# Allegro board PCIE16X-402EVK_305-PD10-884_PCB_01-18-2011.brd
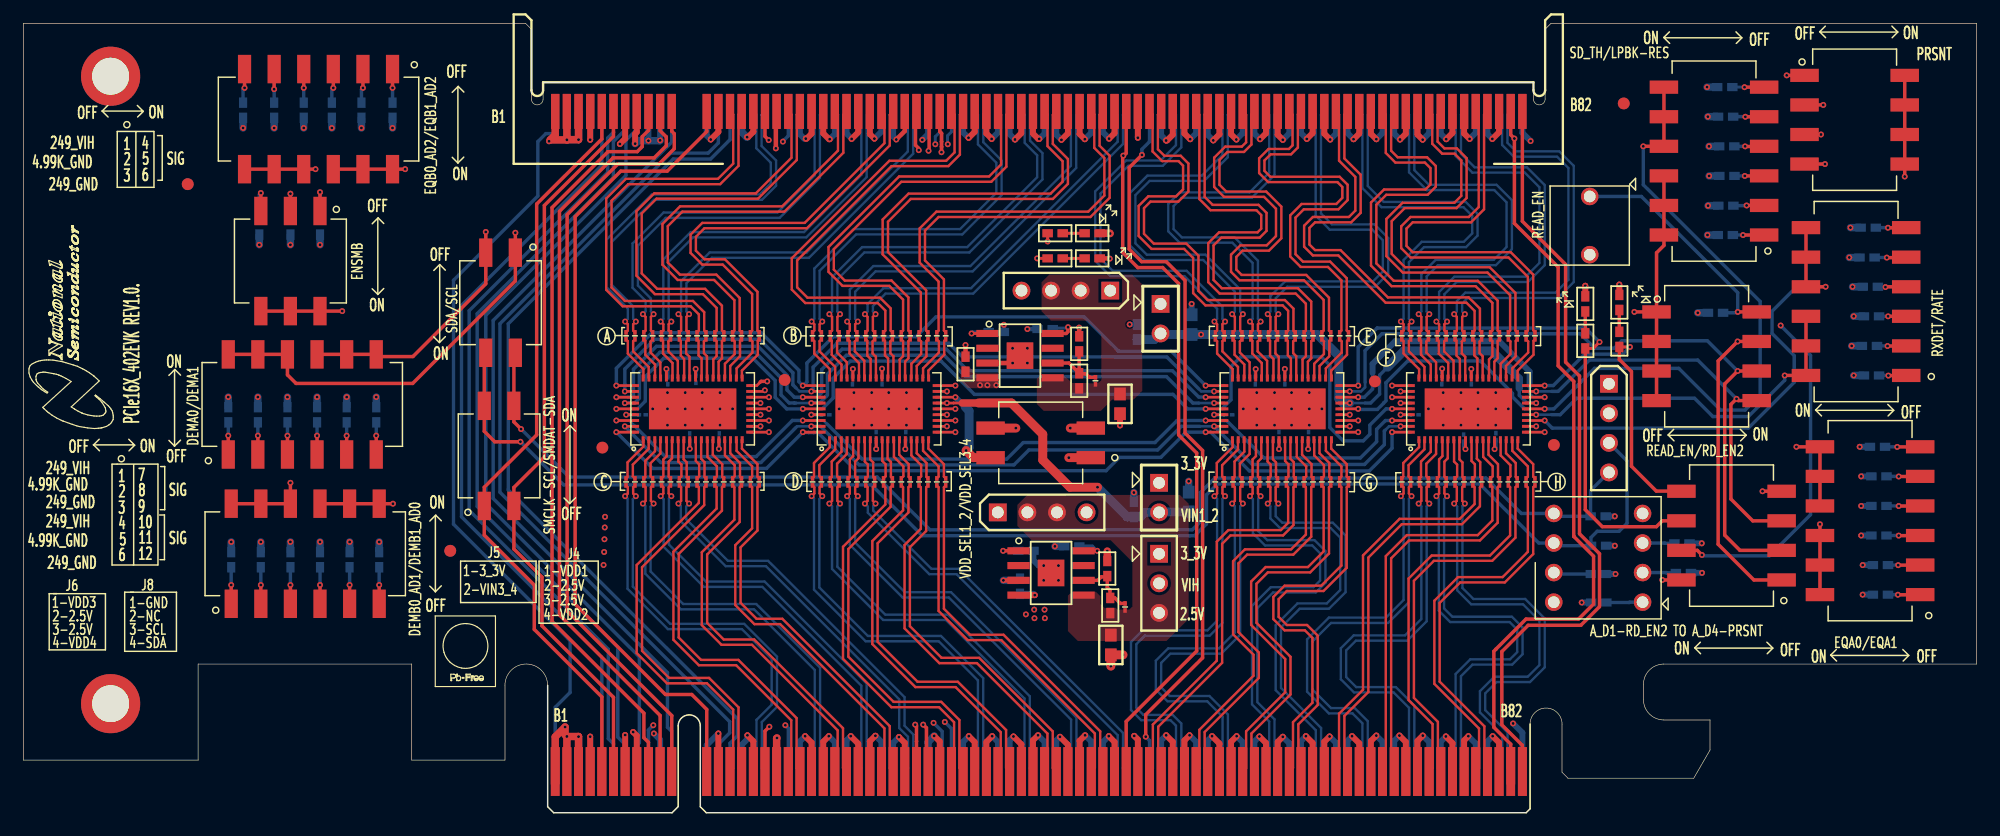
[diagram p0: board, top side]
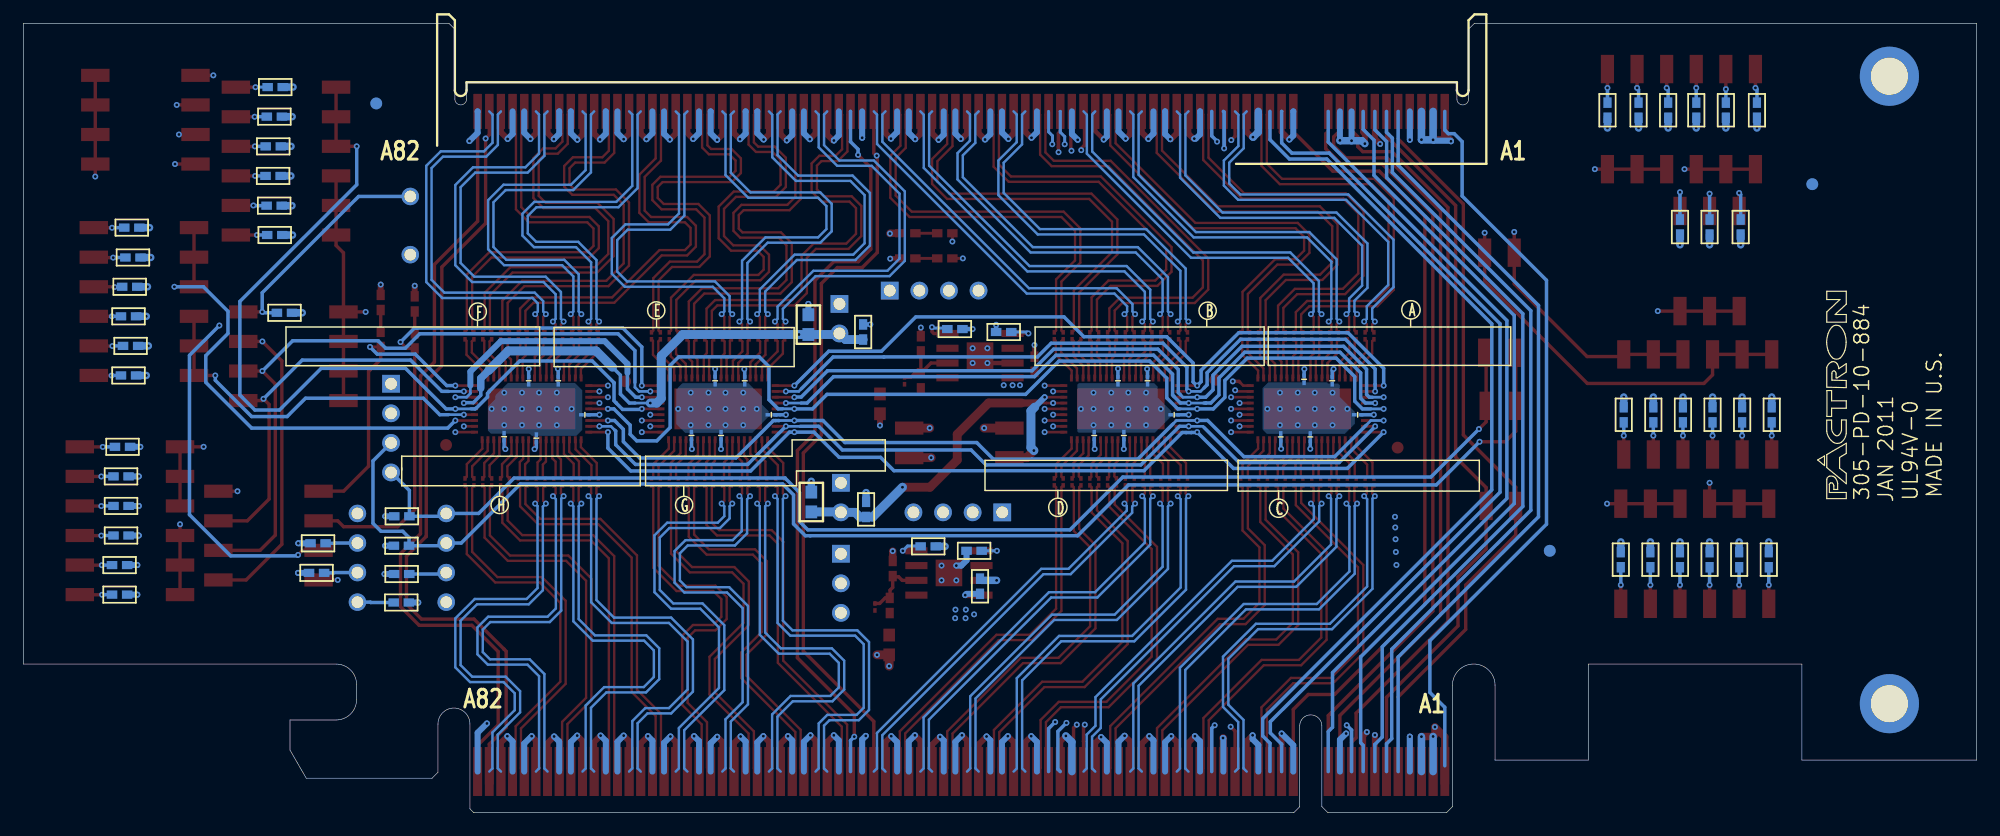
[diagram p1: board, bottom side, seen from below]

Outline 167.64 x 67.82 mm; copper layers: TOP, GND1, POWER1, POWER2, GND2, BOTTOM. Coordinates in mm from the lower left corner of the outline.
Outline path: 0,67.82 0,4.52 15,4.52 15,12.77 33.33,12.77 33.33,4.52 41.34,4.52 41.34,10.95 arc(43.16,12.77) 44.99,10.95 44.99,0.52 45.51,0 55.68,0 56.2,0.52 56.2,7.47 arc(57.15,8.42) 58.1,7.47 58.1,0.51 58.61,0 128.98,0 129.31,0.34 129.31,7.62 arc(130.68,8.99) 132.05,7.62 132.05,3.47 132.56,2.97 143.36,2.97 144.75,5.39 144.75,7.97 140.79,7.97 arc(139.55,8.48) 139.04,9.72 139.04,11.02 arc(139.55,12.26) 140.79,12.77 167.64,12.77 167.64,67.82 131.11,67.82 130.6,67.31 130.6,61.31 arc(130.1,60.81) 129.6,61.31 129.6,62.74 44.61,62.74 44.61,61.31 arc(44.11,60.81) 43.61,61.31 43.61,67.31 43.1,67.82 0,67.82

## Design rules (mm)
net group 3_3V: nets N14347847 N14379914
net group A_D1: nets A_D1 N144905650
net group A_D2: nets A_D2 N144912360
net group A_D3: nets A_D3 N144909880
net group A_D4: nets A_D4 N144914850
net group PERN0: nets N708449616 PERN0
net group PERN0_C: nets N144793501 PERN0_C
net group PERN1: nets N708449621 PERN1
net group PERN1_C: nets N144768421 PERN1_C
net group PERN2: nets N708449625 PERN2
net group PERN2_C: nets N144768181 PERN2_C
net group PERN3: nets N708449629 PERN3
net group PERN3_C: nets N144794701 PERN3_C
net group PERN4: nets N708449635 PERN4
net group PERN4_C: nets N144796981 PERN4_C
net group PERN5: nets N708449639 PERN5
net group PERN5_C: nets N144780601 PERN5_C
net group PERN6: nets N708449643 PERN6
net group PERN6_C: nets N144778981 PERN6_C
net group PERN7: nets N708449647 PERN7
net group PERN7_C: nets N144766261 PERN7_C
net group PERN8: nets N708449652 PERN8
net group PERN8_C: nets N144777781 PERN8_C
net group PERN9: nets N708449656 PERN9
net group PERN9_C: nets N144778201 PERN9_C
net group PERN10: nets N708449660 PERN10
net group PERN10_C: nets N144778741 PERN10_C
net group PERN11: nets N708449664 PERN11
net group PERN11_C: nets N144777421 PERN11_C
net group PERN12: nets N708449668 PERN12
net group PERN12_C: nets N144796741 PERN12_C
net group PERN13: nets N708449672 PERN13
net group PERN13_C: nets N144769921 PERN13_C
net group PERN14: nets N708449676 PERN14
net group PERN14_C: nets N144775501 PERN14_C
net group PERN15: nets N708449680 PERN15
net group PERN15_C: nets N144767221 PERN15_C
net group PERP0: nets N708449615 PERP0
net group PERP0_C: nets N144792241 PERP0_C
net group PERP1: nets N708449620 PERP1
net group PERP1_C: nets N144791101 PERP1_C
net group PERP2: nets N708449624 PERP2
net group PERP2_C: nets N144794401 PERP2_C
net group PERP3: nets N708449628 PERP3
net group PERP3_C: nets N144773581 PERP3_C
net group PERP4: nets N708449634 PERP4
net group PERP4_C: nets N144792841 PERP4_C
net group PERP5: nets N708449638 PERP5
net group PERP5_C: nets N144771181 PERP5_C
net group PERP6: nets N708449642 PERP6
net group PERP6_C: nets N144780361 PERP6_C
net group PERP7: nets N708449646 PERP7
net group PERP7_C: nets N144773341 PERP7_C
net group PERP8: nets N708449651 PERP8
net group PERP8_C: nets N144769021 PERP8_C
net group PERP9: nets N708449655 PERP9
net group PERP9_C: nets N144788821 PERP9_C
net group PERP10: nets N708449659 PERP10
net group PERP10_C: nets N144768781 PERP10_C
net group PERP11: nets N708449663 PERP11
net group PERP11_C: nets N144772741 PERP11_C
net group PERP12: nets N708449667 PERP12
net group PERP12_C: nets N144777181 PERP12_C
net group PERP13: nets N708449671 PERP13
net group PERP13_C: nets N144766561 PERP13_C
net group PERP14: nets N708449675 PERP14
net group PERP14_C: nets N144795421 PERP14_C
net group PERP15: nets N708449679 PERP15
net group PERP15_C: nets N144788221 PERP15_C
net group PETN0: nets N708449696 PETN0
net group PETN0_C: nets N144795060 PETN0_C
net group PETN1: nets N7084496101 PETN1
net group PETN1_C: nets N144774480 PETN1_C
net group PETN2: nets N7084496105 PETN2
net group PETN2_C: nets N144776640 PETN2_C
net group PETN3: nets N7084496109 PETN3
net group PETN3_C: nets N144771900 PETN3_C
net group PETN4: nets N7084496115 PETN4
net group PETN4_C: nets N144790620 PETN4_C
net group PETN5: nets N7084496119 PETN5
net group PETN5_C: nets N144770280 PETN5_C
net group PETN6: nets N7084496123 PETN6
net group PETN6_C: nets N144771420 PETN6_C
net group PETN7: nets N7084496127 PETN7
net group PETN7_C: nets N144775140 PETN7_C
net group PETN8: nets N7084496132 PETN8
net group PETN8_C: nets N144795720 PETN8_C
net group PETN9: nets N7084496136 PETN9
net group PETN9_C: nets N144776160 PETN9_C
net group PETN10: nets N7084496140 PETN10
net group PETN10_C: nets N144770880 PETN10_C
net group PETN11: nets N7084496144 PETN11
net group PETN11_C: nets N144790260 PETN11_C
net group PETN12: nets N7084496148 PETN12
net group PETN12_C: nets N144772500 PETN12_C
net group PETN13: nets N7084496152 PETN13
net group PETN13_C: nets N144778500 PETN13_C
net group PETN14: nets N7084496156 PETN14
net group PETN14_C: nets N144774000 PETN14_C
net group PETN15: nets N7084496160 PETN15
net group PETN15_C: nets N144791880 PETN15_C
net group PETP0: nets N708449695 PETP0
net group PETP0_C: nets N144769680 PETP0_C
net group PETP1: nets N7084496100 PETP1
net group PETP1_C: nets N144776880 PETP1_C
net group PETP2: nets N7084496104 PETP2
net group PETP2_C: nets N144766980 PETP2_C
net group PETP3: nets N7084496108 PETP3
net group PETP3_C: nets N144779460 PETP3_C
net group PETP4: nets N7084496114 PETP4
net group PETP4_C: nets N144779220 PETP4_C
net group PETP5: nets N7084496118 PETP5
net group PETP5_C: nets N144796260 PETP5_C
net group PETP6: nets N7084496122 PETP6
net group PETP6_C: nets N144789780 PETP6_C
net group PETP7: nets N7084496126 PETP7
net group PETP7_C: nets N144765660 PETP7_C
net group PETP8: nets N7084496131 PETP8
net group PETP8_C: nets N144789240 PETP8_C
net group PETP9: nets N7084496135 PETP9
net group PETP9_C: nets N144794040 PETP9_C
net group PETP10: nets N7084496139 PETP10
net group PETP10_C: nets N144770640 PETP10_C
net group PETP11: nets N7084496143 PETP11
net group PETP11_C: nets N144774240 PETP11_C
net group PETP12: nets N7084496147 PETP12
net group PETP12_C: nets N144793080 PETP12_C
net group PETP13: nets N7084496151 PETP13
net group PETP13_C: nets N144780060 PETP13_C
net group PETP14: nets N7084496155 PETP14
net group PETP14_C: nets N144767760 PETP14_C
net group PETP15: nets N7084496159 PETP15
net group PETP15_C: nets N144772140 PETP15_C
net group VOUT1_2: nets N14347575 VOUT1_2
net group VOUT3_4: nets N14379574 VOUT3_4
net group SCL: nets N14519010 N14693554 N143603151 N143605671 N144870781 N144872810 N144872813 N144873671 N144875811 N144883340 N144883343 N144883781 N144885701 N144890181 N144891221 SCL SDA

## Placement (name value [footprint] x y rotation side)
C1  0.1uF  [0201]  57.19 32.28 270 bottom
C2  0.1uF  [0201]  53.12 34.19 180 bottom
C3  0.1uF  [0201]  57.72 37.23 90 bottom
C4  0.1uF  [0201]  55.31 37.11 90 bottom
C5  0.1uF  [0201]  59.73 32.28 270 bottom
C6  0.1uF  [0201]  73.7 37.11 90 bottom
C7  0.1uF  [0201]  71.16 37.11 90 bottom
C8  0.1uF  [0201]  68.87 34.19 180 bottom
C9  0.1uF  [0201]  73.19 32.41 270 bottom
C10  0.1uF  [0201]  75.73 32.41 270 bottom
C11  0.1uF  [0201]  110.3 32.41 270 bottom
C12  0.1uF  [0201]  107.76 32.41 270 bottom
C13  0.1uF  [0201]  103.44 34.19 180 bottom
C14  0.1uF  [0201]  108.27 37.11 90 bottom
C15  0.1uF  [0201]  105.73 37.11 90 bottom
C16  0.1uF  [0201]  126.38 32.31 270 bottom
C17  0.1uF  [0201]  123.61 32.18 270 bottom
C18  0.1uF  [0201]  119.44 34.19 180 bottom
C19  0.1uF  [0201]  124.27 37.11 90 bottom
C20  0.1uF  [0201]  121.73 37.11 90 bottom
C21  10uF  [0603]  100.01 26.69 270 bottom
C22  10uF  [0603]  100.27 41.93 270 bottom
C23  4.7uF  [0402]  85.53 19.45 270 bottom
C24  4.7uF  [0402]  80.86 38.53 270 top
C25  0.01uF  [0402]  86.04 22.5 0 bottom
C26  0.01uF  [0402]  83.5 41.3 0 bottom
C27  10uF  [0603]  93.33 14.41 270 top
C28  10uF  [0603]  94.12 35.12 270 top
C29  1nF  [0201]  94.55 17.68 90 top
C30  1nF  [0201]  92.01 37.11 90 top
C31  0.22uF  [0201]  57.82 28.42 90 top
C32  0.22uF  [0201]  58.59 28.42 90 top
C33  0.22uF  [0201]  59.35 28.42 90 top
C34  0.22uF  [0201]  60.11 28.42 90 top
C35  0.22uF  [0201]  60.87 28.42 90 top
C36  0.22uF  [0201]  61.63 28.42 90 top
C37  0.22uF  [0201]  62.4 28.42 90 top
C38  0.22uF  [0201]  63.16 28.42 90 top
C39  0.22uF  [0201]  73.83 28.42 90 top
C40  0.22uF  [0201]  74.59 28.42 90 top
C41  0.22uF  [0201]  75.35 28.42 90 top
C42  0.22uF  [0201]  76.11 28.42 90 top
C43  0.22uF  [0201]  76.87 28.42 90 top
C44  0.22uF  [0201]  77.64 28.42 90 top
C45  0.22uF  [0201]  78.4 28.42 90 top
C46  0.22uF  [0201]  79.16 28.42 90 top
C47  0.22uF  [0201]  108.39 28.42 90 top
C48  0.22uF  [0201]  109.16 28.42 90 top
C49  0.22uF  [0201]  109.92 28.42 90 top
C50  0.22uF  [0201]  110.68 28.42 90 top
C51  0.22uF  [0201]  111.44 28.42 90 top
C52  0.22uF  [0201]  112.2 28.42 90 top
C53  0.22uF  [0201]  112.97 28.42 90 top
C54  0.22uF  [0201]  113.73 28.42 90 top
C55  0.22uF  [0201]  124.4 28.42 90 top
C56  0.22uF  [0201]  125.16 28.42 90 top
C57  0.22uF  [0201]  125.92 28.42 90 top
C58  0.22uF  [0201]  126.68 28.42 90 top
C59  0.22uF  [0201]  127.44 28.42 90 top
C60  0.22uF  [0201]  128.21 28.42 90 top
C61  0.22uF  [0201]  128.97 28.42 90 top
C62  0.22uF  [0201]  129.73 28.42 90 top
C63  0.22uF  [0201]  51.73 28.42 270 top
C64  0.22uF  [0201]  52.49 28.42 270 top
C65  0.22uF  [0201]  53.25 28.42 270 top
C66  0.22uF  [0201]  54.01 28.42 270 top
C67  0.22uF  [0201]  54.78 28.42 270 top
C68  0.22uF  [0201]  55.54 28.42 270 top
C69  0.22uF  [0201]  56.3 28.42 270 top
C70  0.22uF  [0201]  57.06 28.42 270 top
C71  0.22uF  [0201]  67.73 28.42 270 top
C72  0.22uF  [0201]  68.49 28.42 270 top
C73  0.22uF  [0201]  69.25 28.42 270 top
C74  0.22uF  [0201]  70.02 28.42 270 top
C75  0.22uF  [0201]  70.78 28.42 270 top
C76  0.22uF  [0201]  71.54 28.42 270 top
C77  0.22uF  [0201]  72.3 28.42 270 top
C78  0.22uF  [0201]  73.06 28.42 270 top
C79  0.22uF  [0201]  102.3 28.42 270 top
C80  0.22uF  [0201]  103.06 28.42 270 top
C81  0.22uF  [0201]  103.82 28.42 270 top
C82  0.22uF  [0201]  104.58 28.42 270 top
C83  0.22uF  [0201]  105.35 28.42 270 top
C84  0.22uF  [0201]  106.11 28.42 270 top
C85  0.22uF  [0201]  106.87 28.42 270 top
C86  0.22uF  [0201]  107.63 28.42 270 top
C87  0.22uF  [0201]  118.3 28.42 270 top
C88  0.22uF  [0201]  119.06 28.42 270 top
C89  0.22uF  [0201]  119.82 28.42 270 top
C90  0.22uF  [0201]  120.59 28.42 270 top
C91  0.22uF  [0201]  121.35 28.42 270 top
C92  0.22uF  [0201]  122.11 28.42 270 top
C93  0.22uF  [0201]  122.87 28.42 270 top
C94  0.22uF  [0201]  123.63 28.42 270 top
C95  0.22uF  [0201]  57.82 40.97 270 top
C96  0.22uF  [0201]  58.59 40.97 270 top
C97  0.22uF  [0201]  59.35 40.97 270 top
C98  0.22uF  [0201]  60.11 40.97 270 top
C99  0.22uF  [0201]  60.87 40.97 270 top
C100  0.22uF  [0201]  61.63 40.97 270 top
C101  0.22uF  [0201]  62.4 40.97 270 top
C102  0.22uF  [0201]  63.16 40.97 270 top
C103  0.22uF  [0201]  73.83 40.97 270 top
C104  0.22uF  [0201]  74.59 40.97 270 top
C105  0.22uF  [0201]  75.35 40.97 270 top
C106  0.22uF  [0201]  76.11 40.97 270 top
C107  0.22uF  [0201]  76.87 40.97 270 top
C108  0.22uF  [0201]  77.64 40.97 270 top
C109  0.22uF  [0201]  78.4 40.97 270 top
C110  0.22uF  [0201]  79.16 40.97 270 top
C111  0.22uF  [0201]  108.39 40.97 270 top
C112  0.22uF  [0201]  109.16 40.97 270 top
C113  0.22uF  [0201]  109.92 40.97 270 top
C114  0.22uF  [0201]  110.68 40.97 270 top
C115  0.22uF  [0201]  111.44 40.97 270 top
C116  0.22uF  [0201]  112.2 40.97 270 top
C117  0.22uF  [0201]  112.97 40.97 270 top
C118  0.22uF  [0201]  113.73 40.97 270 top
C119  0.22uF  [0201]  124.4 40.97 270 top
C120  0.22uF  [0201]  125.16 40.97 270 top
C121  0.22uF  [0201]  125.92 40.97 270 top
C122  0.22uF  [0201]  126.68 40.97 270 top
C123  0.22uF  [0201]  127.44 40.97 270 top
C124  0.22uF  [0201]  128.21 40.97 270 top
C125  0.22uF  [0201]  128.97 40.97 270 top
C126  0.22uF  [0201]  129.73 40.97 270 top
C127  0.22uF  [0201]  51.73 40.97 90 top
C128  0.22uF  [0201]  52.49 40.97 90 top
C129  0.22uF  [0201]  53.25 40.97 90 top
C130  0.22uF  [0201]  54.01 40.97 90 top
C131  0.22uF  [0201]  54.78 40.97 90 top
C132  0.22uF  [0201]  55.54 40.97 90 top
C133  0.22uF  [0201]  56.3 40.97 90 top
C134  0.22uF  [0201]  57.06 40.97 90 top
C135  0.22uF  [0201]  67.73 40.97 90 top
C136  0.22uF  [0201]  68.49 40.97 90 top
C137  0.22uF  [0201]  69.25 40.97 90 top
C138  0.22uF  [0201]  70.02 40.97 90 top
C139  0.22uF  [0201]  70.78 40.97 90 top
C140  0.22uF  [0201]  71.54 40.97 90 top
C141  0.22uF  [0201]  72.3 40.97 90 top
C142  0.22uF  [0201]  73.06 40.97 90 top
C143  0.22uF  [0201]  102.3 40.97 90 top
C144  0.22uF  [0201]  103.06 40.97 90 top
C145  0.22uF  [0201]  103.82 40.97 90 top
C146  0.22uF  [0201]  104.58 40.97 90 top
C147  0.22uF  [0201]  105.35 40.97 90 top
C148  0.22uF  [0201]  106.11 40.97 90 top
C149  0.22uF  [0201]  106.87 40.97 90 top
C150  0.22uF  [0201]  107.63 40.97 90 top
C151  0.22uF  [0201]  118.3 40.97 90 top
C152  0.22uF  [0201]  119.06 40.97 90 top
C153  0.22uF  [0201]  119.82 40.97 90 top
C154  0.22uF  [0201]  120.59 40.97 90 top
C155  0.22uF  [0201]  121.35 40.97 90 top
C156  0.22uF  [0201]  122.11 40.97 90 top
C157  0.22uF  [0201]  122.87 40.97 90 top
C158  0.22uF  [0201]  123.63 40.97 90 top
C160  1uF  [0402]  95.31 26.06 270 bottom
C161  1uF  [0402]  95.57 41.3 270 bottom
D1  SML-P12PTT86  [SML-P12PTT86_0402]  91.73 49.78 180 top
D2  SML-P12PTT86  [SML-P12PTT86_0402]  91.73 47.62 180 top
D3  SML-P12PTT86  [SML-P12PTT86_0402]  134.05 43.71 270 top
D4  SML-P12PTT86  [SML-P12PTT86_0402]  136.97 43.84 270 top
J1  -  [PCIE_16X_EDGE_FINGER]  53.65 3.54 0 top
J2  -  [NWE82DHRN-T9410]  86.94 68.58 0 top
J3  2 HEADER  [2_HEADER]  97.47 28.34 270 top
J4  4 HEADER  [4_HEADER]  83.63 25.8 0 top
J5  2 HEADER  [2_HEADER]  97.6 43.71 270 top
J6  4 HEADER  [4_HEADER]  93.28 44.85 180 top
J7  3 HEADER  [3_HEADER]  97.47 22.25 270 top
J8  4 HEADER  [4_HEADER]  136.08 36.85 270 top
J9  4808-3004-CP  [DIP8]  135.16 21.9 90 top
NOREF  -  [unnamed]  14.11 54 0 top
NOREF#2  -  [unnamed]  36.64 22.5 0 top
NOREF#3  -  [unnamed]  115.99 37.06 0 top
NOREF#4  -  [unnamed]  49.7 31.37 0 top
NOREF#5  -  [unnamed]  7.49 63.27 0 top
NOREF#6  -  [unnamed]  7.49 9.37 0 top
NOREF#7  -  [unnamed]  65.34 37.18 0 top
NOREF#8  -  [#2]  15 12.77 0 top
NOREF#9  -  [unnamed]  137.35 60.93 0 top
NOREF#10  -  [#2]  33.33 4.52 0 top
NOREF#11  -  [#2]  167.64 12.77 90 top
NOREF#12  -  [#2]  0 68.58 0 top
NOREF#13  -  [unnamed]  131.36 31.59 0 top
NOREF#14  -  [#2]  0 4.52 90 top
NOREF#15  -  [#2]  0 4.52 0 top
NOREF#16  -  [unnamed]  137.35 60.93 180 bottom
NOREF#17  -  [unnamed]  36.64 22.5 180 bottom
NOREF#18  -  [unnamed]  14.11 54 180 bottom
R1  1.5k  [0402]  93.28 17.8 270 top
R2  1k  [0402]  93.03 20.98 270 top
R3  51k  [0402]  89.98 22.88 0 bottom
R4  1.5k  [0402]  90.61 37.11 270 top
R5  1k  [0402]  90.61 40.28 270 top
R6  51k  [0402]  87.69 41.55 0 bottom
R7  220  [0402]  88.56 49.78 180 top
R8  220  [0402]  88.56 47.62 180 top
R9  220  [0402]  134.05 40.54 270 top
R10  220  [0402]  136.97 40.66 270 top
R11  249  [0402]  31.69 60.35 90 bottom
R12  4.99k  [0402]  29.02 60.35 90 bottom
R13  249  [0402]  26.48 60.35 90 bottom
R14  249  [0402]  24.07 60.35 90 bottom
R15  4.99k  [0402]  21.53 60.35 90 bottom
R16  249  [0402]  18.86 60.35 90 bottom
R17  249  [0402]  25.46 50.31 90 bottom
R18  4.99k  [0402]  22.92 50.31 90 bottom
R19  249  [0402]  20.26 50.31 90 bottom
R20  249  [0402]  17.59 34.19 270 bottom
R21  4.99k  [0402]  20.13 34.19 270 bottom
R22  249  [0402]  22.67 34.19 270 bottom
R23  249  [0402]  25.21 34.19 270 bottom
R24  4.99k  [0402]  27.75 34.19 270 bottom
R25  249  [0402]  30.29 34.19 270 bottom
R26  249  [0402]  17.84 21.74 270 bottom
R27  4.99k  [0402]  20.38 21.74 270 bottom
R28  249  [0402]  22.92 21.74 270 bottom
R29  249  [0402]  25.46 21.74 270 bottom
R30  4.99k  [0402]  28 21.74 270 bottom
R31  249  [0402]  30.54 21.74 270 bottom
R32  249  [0402]  146.06 49.63 0 bottom
R33  4.99k  [0402]  146.11 52.15 0 bottom
R34  249  [0402]  146.2 54.7 0 bottom
R35  249  [0402]  146.19 57.25 0 bottom
R36  4.99k  [0402]  146.09 59.8 0 bottom
R37  249  [0402]  146.02 62.34 0 bottom
R38  249  [0402]  158.61 37.56 0 bottom
R39  4.99k  [0402]  158.43 40.1 0 bottom
R40  249  [0402]  158.61 42.64 0 bottom
R41  249  [0402]  158.51 45.18 0 bottom
R42  4.99k  [0402]  158.23 47.7 0 bottom
R43  249  [0402]  158.33 50.26 0 bottom
R44  249  [0402]  159.38 18.73 0 bottom
R45  4.99k  [0402]  159.38 21.27 0 bottom
R46  249  [0402]  159.25 23.81 0 bottom
R47  249  [0402]  159.25 26.35 0 bottom
R48  4.99k  [0402]  159.25 28.89 0 bottom
R49  249  [0402]  159.12 31.43 0 bottom
R50  1k  [0402]  135.2 18.06 0 bottom
R51  1k  [0402]  142.47 20.61 180 bottom
R52  1k  [0402]  142.35 23.15 180 bottom
R53  1k  [0402]  145.22 42.95 0 bottom
R54  1k  [0402]  135.17 20.51 0 bottom
R55  2k  [0402]  135.19 22.94 0 bottom
R56  2k  [0402]  135.16 25.47 0 bottom
SW1  -  [219-6MST]  25.34 59.59 180 top
SW2  -  [219-3MST]  22.92 47.39 180 top
SW3  -  [219-6MST]  23.94 35.07 0 top
SW4  -  [219-2MST]  40.96 43.81 180 top
SW5  -  [219-6MST]  24.19 22.25 0 top
SW6  -  [219-6MST]  145.1 55.98 90 top
SW7  -  [219-2MST]  87.31 31.77 90 top
SW8  -  [219-4MST]  144.46 40.48 270 top
SW9  -  [219-4MST]  146.6 22.54 90 top
SW10  -  [219-6MST]  157.29 43.91 90 top
SW11  -  [219-6MST]  158.49 25.08 90 top
SW12  -  [219-2MST]  40.83 30.65 0 top
SW13  -  [EVQ-21505R]  134.43 50.44 270 top
SW14  -  [219-4MST]  157.16 60.8 270 top
U1  DS80PCI402  [54_LLP]  57.44 34.69 0 top
U2  DS80PCI402  [54_LLP]  73.44 34.69 0 top
U3  DS80PCI402  [54_LLP]  108.01 34.69 0 top
U4  DS80PCI402  [54_LLP]  124.02 34.69 0 top
U5  LP3878-ADJ  [PSOP-8]  88.2 20.6 0 top
U6  LP3878-ADJ  [PSOP-8]  85.53 39.27 0 top

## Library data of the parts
C1-C20 = C: signal model: DEFAULT_CAPACITOR_100000pF_2_1
C21 C22 C27 C28 = C: signal model: DEFAULT_CAPACITOR_1e+07pF_2_1
C23 C24 = C: signal model: DEFAULT_CAPACITOR_4.7e+06pF_2_1
C25 C26 = C: signal model: DEFAULT_CAPACITOR_10000pF_2_1
C29 C30 = C: signal model: DEFAULT_CAPACITOR_1000pF_2_1
C31-C158 = C: signal model: DEFAULT_CAPACITOR_220000pF_2_1
C160 C161 = C: signal model: DEFAULT_CAPACITOR_1e+06pF_2_1
D1-D4 = 1091QM_0
J1 = PCIE_16X_EDGE_FINGER
J2 = NWE82DHRN-T9410
J3 J5 = HEADER 2
J4 J6 J8 = 4 HEADER
J7 = HEADER 3
J9 = DIP8 SOCKET
R1 R4 = RESISTOR/SM: signal model: DEFAULT_RESISTOR_1500OHM_2_1
R2 R5 R53 R54 = RESISTOR/SM: signal model: DEFAULT_RESISTOR_1000OHM_2_1
R3 R6 = RESISTOR/SM: signal model: DEFAULT_RESISTOR_51000OHM_2_1
R7 R8 = R_0: signal model: DEFAULT_RESISTOR_0.001OHM_2_1
R9 R10 = R_0: signal model: DEFAULT_RESISTOR_220OHM_2_1
R11-R13 R16 R37 R38 R42 = RESISTOR: signal model: DEFAULT_RESISTOR_0.001OHM_2_1
R14 R15 R17-R36 R39-R41 R43-R49 = RESISTOR: signal model: DEFAULT_RESISTOR_33OHM_2_1
R50-R52 = RESISTOR: signal model: DEFAULT_RESISTOR_1000OHM_2_1
R55 R56 = RESISTOR/SM: signal model: DEFAULT_RESISTOR_2000OHM_2_1
SW1 SW3 SW5 SW6 SW10 SW11 = SW DIP-6/SM
SW2 = SW DIP-3/SM
SW4 SW7 SW12 = SW DIP-2/SM
SW8 SW9 SW14 = SW DIP-4/SM
SW13 = SW PUSHBUTTON-SPST
U1-U4 = DS80PCI402
U5 U6 = LP3878-ADJ_0

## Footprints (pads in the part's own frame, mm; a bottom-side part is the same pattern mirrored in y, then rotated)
2_HEADER
  rect 1.524x1.524 hole 1.016: 1(0,0)
  round 1.524 hole 1.016: 2(2.54,0)
3_HEADER
  rect 1.524x1.524 hole 1.016: 1(0,0)
  round 1.524 hole 1.016: 2(2.54,0) 3(5.08,0)
4_HEADER
  rect 1.524x1.524 hole 1.016: 1(0,0)
  round 1.524 hole 1.016: 2(2.54,0) 3(5.08,0) 4(7.62,0)
54_LLP
  rect 0.25x0.6 smd: 1(-4.25,-2.65) 2(-3.75,-2.65) 3(-3.25,-2.65) 4(-2.75,-2.65) 5(-2.25,-2.65) 6(-1.75,-2.65) 7(-1.25,-2.65) 8(-0.75,-2.65) 9(-0.25,-2.65) 10(0.25,-2.65) 11(0.75,-2.65) 12(1.25,-2.65) 13(1.75,-2.65) 14(2.25,-2.65) 15(2.75,-2.65) 16(3.25,-2.65) 17(3.75,-2.65) 18(4.25,-2.65) 28(4.25,2.65) 29(3.75,2.65) 30(3.25,2.65) 31(2.75,2.65) 32(2.25,2.65) 33(1.75,2.65) 34(1.25,2.65) 35(0.75,2.65) 36(0.25,2.65) 37(-0.25,2.65) 38(-0.75,2.65) 39(-1.25,2.65) 40(-1.75,2.65) 41(-2.25,2.65) 42(-2.75,2.65) 43(-3.25,2.65) 44(-3.75,2.65) 45(-4.25,2.65)
  rect 0.6x0.25 smd: 19(4.9,-2) 20(4.9,-1.5) 21(4.9,-1) 22(4.9,-0.5) 23(4.9,0) 24(4.9,0.5) 25(4.9,1) 26(4.9,1.5) 27(4.9,2) 46(-4.9,2) 47(-4.9,1.5) 48(-4.9,1) 49(-4.9,0.5) 50(-4.9,0) 51(-4.9,-0.5) 52(-4.9,-1) 53(-4.9,-1.5) 54(-4.9,-2)
  rect 7.5x3.51 smd: 55(0,0)
0201
  rect 0.4x0.297 smd: 1(-0.3,0) 2(0.3,0)
219-2MST
  rect 1.13x2.44 smd: 1(-1.27,-4.3) 2(1.27,-4.3) 3(1.27,4.3) 4(-1.27,4.3)
219-3MST
  rect 1.13x2.44 smd: 1(-2.54,-4.3) 2(0,-4.3) 3(2.54,-4.3) 4(2.54,4.3) 5(0,4.3) 6(-2.54,4.3)
219-4MST
  rect 1.13x2.44 smd: 1(-2.54,-4.3) 2(0,-4.3) 3(2.54,-4.3) 4(5.08,-4.3) 5(5.08,4.3) 6(2.54,4.3) 7(0,4.3) 8(-2.54,4.3)
219-6MST
  rect 1.13x2.44 smd: 1(-6.35,-4.3) 2(-3.81,-4.3) 3(-1.27,-4.3) 4(1.27,-4.3) 5(3.81,-4.3) 6(6.35,-4.3) 7(6.35,4.3) 8(3.81,4.3) 9(1.27,4.3) 10(-1.27,4.3) 11(-3.81,4.3) 12(-6.35,4.3)
0402
  rect 0.9x0.7 smd: 1(-0.65,0) 2(0.65,0)
0603
  rect 1.1x1 smd: 1(-0.85,0) 2(0.85,0)
DIP8
  round 1.5 hole 1: 1(-3.81,-3.81) 2(-1.27,-3.81) 3(1.27,-3.81) 4(3.81,-3.81) 5(3.81,3.81) 6(1.27,3.81) 7(-1.27,3.81) 8(-3.81,3.81)
EVQ-21505R
  round 1.5 hole 1: 1(-2.5,0) 2(2.5,0)
NWE82DHRN-T9410
  rect 0.7x3 smd: A1(-41.29,-8.332) A2(-40.29,-8.332) A3(-39.29,-8.332) A4(-38.29,-8.332) A5(-37.29,-8.332) A6(-36.29,-8.332) A7(-35.29,-8.332) A8(-34.29,-8.332) A9(-33.29,-8.332) A10(-32.29,-8.332) A11(-31.29,-8.332) A12(-28.29,-8.332) A13(-27.29,-8.332) A14(-26.29,-8.332) A15(-25.29,-8.332) A16(-24.29,-8.332) A17(-23.29,-8.332) A18(-22.29,-8.332) A19(-21.29,-8.332) A20(-20.29,-8.332) A21(-19.29,-8.332) A22(-18.29,-8.332) A23(-17.29,-8.332) A24(-16.29,-8.332) A25(-15.29,-8.332) A26(-14.29,-8.332) A27(-13.29,-8.332) A28(-12.29,-8.332) A29(-11.29,-8.332) A30(-10.29,-8.332) A31(-9.29,-8.332) A32(-8.29,-8.332) A33(-7.29,-8.332) A34(-6.29,-8.332) A35(-5.29,-8.332) A36(-4.29,-8.332) A37(-3.29,-8.332) A38(-2.29,-8.332) A39(-1.29,-8.332) A40(-0.29,-8.332) A41(0.71,-8.332) A42(1.71,-8.332) A43(2.71,-8.332) A44(3.71,-8.332) A45(4.71,-8.332) A46(5.71,-8.332) A47(6.71,-8.332) A48(7.71,-8.332) A49(8.71,-8.332) A50(9.71,-8.332) A51(10.71,-8.332) A52(11.71,-8.332) A53(12.71,-8.332) A54(13.71,-8.332) A55(14.71,-8.332) A56(15.71,-8.332) A57(16.71,-8.332) A58(17.71,-8.332) A59(18.71,-8.332) A60(19.71,-8.332) A61(20.71,-8.332) A62(21.71,-8.332) A63(22.71,-8.332) A64(23.71,-8.332) A65(24.71,-8.332) A66(25.71,-8.332) A67(26.71,-8.332) A68(27.71,-8.332) A69(28.71,-8.332) A70(29.71,-8.332) A71(30.71,-8.332) A72(31.71,-8.332) A73(32.71,-8.332) A74(33.71,-8.332) A75(34.71,-8.332) A76(35.71,-8.332) A77(36.71,-8.332) A78(37.71,-8.332) A79(38.71,-8.332) A80(39.71,-8.332) A81(40.71,-8.332) A82(41.71,-8.332) B1(-41.29,-8.332) B2(-40.29,-8.332) B3(-39.29,-8.332) B4(-38.29,-8.332) B5(-37.29,-8.332) B6(-36.29,-8.332) B7(-35.29,-8.332) B8(-34.29,-8.332) B9(-33.29,-8.332) B10(-32.29,-8.332) B11(-31.29,-8.332) B12(-28.29,-8.332) B13(-27.29,-8.332) B14(-26.29,-8.332) B15(-25.29,-8.332) B16(-24.29,-8.332) B17(-23.29,-8.332) B18(-22.29,-8.332) B19(-21.29,-8.332) B20(-20.29,-8.332) B21(-19.29,-8.332) B22(-18.29,-8.332) B23(-17.29,-8.332) B24(-16.29,-8.332) B25(-15.29,-8.332) B26(-14.29,-8.332) B27(-13.29,-8.332) B28(-12.29,-8.332) B29(-11.29,-8.332) B30(-10.29,-8.332) B31(-9.29,-8.332) B32(-8.29,-8.332) B33(-7.29,-8.332) B34(-6.29,-8.332) B35(-5.29,-8.332) B36(-4.29,-8.332) B37(-3.29,-8.332) B38(-2.29,-8.332) B39(-1.29,-8.332) B40(-0.29,-8.332) B41(0.71,-8.332) B42(1.71,-8.332) B43(2.71,-8.332) B44(3.71,-8.332) B45(4.71,-8.332) B46(5.71,-8.332) B47(6.71,-8.332) B48(7.71,-8.332) B49(8.71,-8.332) B50(9.71,-8.332) B51(10.71,-8.332) B52(11.71,-8.332) B53(12.71,-8.332) B54(13.71,-8.332) B55(14.71,-8.332) B56(15.71,-8.332) B57(16.71,-8.332) B58(17.71,-8.332) B59(18.71,-8.332) B60(19.71,-8.332) B61(20.71,-8.332) B62(21.71,-8.332) B63(22.71,-8.332) B64(23.71,-8.332) B65(24.71,-8.332) B66(25.71,-8.332) B67(26.71,-8.332) B68(27.71,-8.332) B69(28.71,-8.332) B70(29.71,-8.332) B71(30.71,-8.332) B72(31.71,-8.332) B73(32.71,-8.332) B74(33.71,-8.332) B75(34.71,-8.332) B76(35.71,-8.332) B77(36.71,-8.332) B78(37.71,-8.332) B79(38.71,-8.332) B80(39.71,-8.332) B81(40.71,-8.332) B82(41.71,-8.332)
PCIE_16X_EDGE_FINGER
  rect 0.76x3.2 smd: A1(-8,0.5) B81(74,0.5)
  rect 0.76x4.19 smd: A2(-7,0) A3(-6,0) A4(-5,0) A5(-4,0) A6(-3,0) A7(-2,0) A8(-1,0) A9(0,0) A10(1,0) A11(2,0) A12(5,0) A13(6,0) A14(7,0) A15(8,0) A16(9,0) A17(10,0) A18(11,0) A19(12,0) A20(13,0) A21(14,0) A22(15,0) A23(16,0) A24(17,0) A25(18,0) A26(19,0) A27(20,0) A28(21,0) A29(22,0) A30(23,0) A31(24,0) A32(25,0) A33(26,0) A34(27,0) A35(28,0) A36(29,0) A37(30,0) A38(31,0) A39(32,0) A40(33,0) A41(34,0) A42(35,0) A43(36,0) A44(37,0) A45(38,0) A46(39,0) A47(40,0) A48(41,0) A49(42,0) A50(43,0) A51(44,0) A52(45,0) A53(46,0) A54(47,0) A55(48,0) A56(49,0) A57(50,0) A58(51,0) A59(52,0) A60(53,0) A61(54,0) A62(55,0) A63(56,0) A64(57,0) A65(58,0) A66(59,0) A67(60,0) A68(61,0) A69(62,0) A70(63,0) A71(64,0) A72(65,0) A73(66,0) A74(67,0) A75(68,0) A76(69,0) A77(70,0) A78(71,0) A79(72,0) A80(73,0) A81(74,0) A82(75,0) B1(-8,0) B2(-7,0) B3(-6,0) B4(-5,0) B5(-4,0) B6(-3,0) B7(-2,0) B8(-1,0) B9(0,0) B10(1,0) B11(2,0) B12(5,0) B13(6,0) B14(7,0) B15(8,0) B16(9,0) B17(10,0) B18(11,0) B19(12,0) B20(13,0) B21(14,0) B22(15,0) B23(16,0) B24(17,0) B25(18,0) B26(19,0) B27(20,0) B28(21,0) B29(22,0) B30(23,0) B31(24,0) B32(25,0) B33(26,0) B34(27,0) B35(28,0) B36(29,0) B37(30,0) B38(31,0) B39(32,0) B40(33,0) B41(34,0) B42(35,0) B43(36,0) B44(37,0) B45(38,0) B46(39,0) B47(40,0) B48(41,0) B49(42,0) B50(43,0) B51(44,0) B52(45,0) B53(46,0) B54(47,0) B55(48,0) B56(49,0) B57(50,0) B58(51,0) B59(52,0) B60(53,0) B61(54,0) B62(55,0) B63(56,0) B64(57,0) B65(58,0) B66(59,0) B67(60,0) B68(61,0) B69(62,0) B70(63,0) B71(64,0) B72(65,0) B73(66,0) B74(67,0) B75(68,0) B76(69,0) B77(70,0) B78(71,0) B79(72,0) B80(73,0) B82(75,0)
PSOP-8
  rect 1.905x0.61 smd: 1(-2.794,1.905) 2(-2.794,0.635) 3(-2.794,-0.635) 4(-2.794,-1.905) 5(2.794,-1.905) 6(2.794,-0.635) 7(2.794,0.635) 8(2.794,1.905)
  rect 2.286x2.286 smd: 9(0,0)
SML-P12PTT86_0402
  rect 0.9x0.7 smd: 1(-0.65,0) 2(0.65,0)
unnamed
  round 1.016 smd: (0,0)

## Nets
12V: J1.A2 J1.A3 J1.B1 J1.B2 J1.B3 J2.A2 J2.A3 J2.B1 J2.B2 J2.B3
GND: C1.1 C2.1 C3.1 C4.1 C5.1 C6.1 C7.1 C8.1 C9.1 C10.1 C11.1 C12.1 C13.1 C14.1 C15.1 C16.1 C17.1 C18.1 C19.1 C20.1 C21.1 C22.1 C23.1 C24.1 C25.2 C26.2 C27.2 C28.2 C160.1 C161.1 D1.1(CATHODE) D2.1(CATHODE) D3.1(CATHODE) D4.1(CATHODE) J1.A4 J1.A12 J1.A15 J1.A18 J1.A20 J1.A23 J1.A24 J1.A27 J1.A28 J1.A31 J1.A34 J1.A37 J1.A38 J1.A41 J1.A42 J1.A45 J1.A46 J1.A49 J1.A51 J1.A54 J1.A55 J1.A58 J1.A59 J1.A62 J1.A63 J1.A66 J1.A67 J1.A70 J1.A71 J1.A74 J1.A75 J1.A78 J1.A79 J1.A82 J1.B4 J1.B7 J1.B13 J1.B16 J1.B18 J1.B21 J1.B22 J1.B25 J1.B26 J1.B29 J1.B32 J1.B35 J1.B36 J1.B39 J1.B40 J1.B43 J1.B44 J1.B47 J1.B49 J1.B52 J1.B53 J1.B56 J1.B57 J1.B60 J1.B61 J1.B64 J1.B65 J1.B68 J1.B69 J1.B72 J1.B73 J1.B76 J1.B77 J1.B80 J2.A4 J2.A12 J2.A15 J2.A18 J2.A20 J2.A23 J2.A24 J2.A27 J2.A28 J2.A31 J2.A34 J2.A37 J2.A38 J2.A41 J2.A42 J2.A45 J2.A46 J2.A49 J2.A51 J2.A54 J2.A55 J2.A58 J2.A59 J2.A62 J2.A63 J2.A66 J2.A67 J2.A70 J2.A71 J2.A74 J2.A75 J2.A78 J2.A79 J2.A82 J2.B4 J2.B7 J2.B13 J2.B16 J2.B18 J2.B21 J2.B22 J2.B25 J2.B26 J2.B29 J2.B32 J2.B35 J2.B36 J2.B39 J2.B40 J2.B43 J2.B44 J2.B47 J2.B49 J2.B52 J2.B53 J2.B56 J2.B57 J2.B60 J2.B61 J2.B64 J2.B65 J2.B68 J2.B69 J2.B72 J2.B73 J2.B76 J2.B77 J2.B80 J8.1 J9.4 R2.1 R5.1 R12.1 R13.1 R15.1 R16.1 R18.1 R19.1 R21.1 R22.1 R24.1 R25.1 R27.1 R28.1 R30.1 R31.1 R33.1 R34.1 R36.1 R37.1 R39.1 R40.1 R42.1 R43.1 R45.1 R46.1 R48.1 R49.1 R50.1 R51.1 R52.1 SW7.1(A1) SW7.2(A2) SW13.2 U1.55(DAP) U2.55(DAP) U3.55(DAP) U4.55(DAP) U5.3(GND) U5.9(DAP) U6.3(GND) U6.9(DAP)
VDD1: C1.2 C2.2 C3.2 C4.2 C5.2 J4.1 U1.9(VDD#9) U1.14(VDD#14) U1.36(VDD#36) U1.41(VDD#41) U1.51(VDD#51)
VDD2: C6.2 C7.2 C8.2 C9.2 C10.2 J4.4 U2.9(VDD#9) U2.14(VDD#14) U2.36(VDD#36) U2.41(VDD#41) U2.51(VDD#51)
VDD3: C11.2 C12.2 C13.2 C14.2 C15.2 J6.1 U3.9(VDD#9) U3.14(VDD#14) U3.36(VDD#36) U3.41(VDD#41) U3.51(VDD#51)
VDD4: C16.2 C17.2 C18.2 C19.2 C20.2 J6.4 U4.9(VDD#9) U4.14(VDD#14) U4.36(VDD#36) U4.41(VDD#41) U4.51(VDD#51)
VDD_SEL1_2: SW7.4(B1) U1.25(VDD_SEL) U2.25(VDD_SEL)
VDD_SEL3_4: SW7.3(B2) U3.25(VDD_SEL) U4.25(VDD_SEL)
VIN1_2: C21.2 C160.2 J3.2 U1.24(VIN) U2.24(VIN)
VIN3_4: C22.2 C161.2 J5.2 U3.24(VIN) U4.24(VIN)
3_3V: C23.2 C24.2 J1.A9 J1.A10 J1.B8 J2.A9 J2.A10 J2.B8 J3.1 J5.1 J7.1 R3.1 R6.1 U5.4(INPUT) U6.4(INPUT)
3_3VAUX: J1.B10 J2.B10
A_D1: R7.2 SW9.8(B1) U1.27(ALL_DONE)
A_D2: R8.2 SW9.7(B2) U2.27(ALL_DONE)
A_D3: R9.2 SW9.6(B3) U3.27(ALL_DONE)
A_D4: R10.2 SW9.5(B4) U4.27(ALL_DONE)
DEMA0_SDA: SW3.10(B3) SW3.11(B2) SW3.12(B1) SW4.1(A1) U1.49(DEMA0/SDA) U2.49(DEMA0/SDA) U3.49(DEMA0/SDA) U4.49(DEMA0/SDA)
DEMA1_SCL: SW3.7(B6) SW3.8(B5) SW3.9(B4) SW4.2(A2) U1.50(DEMA1/SCL) U2.50(DEMA1/SCL) U3.50(DEMA1/SCL) U4.50(DEMA1/SCL)
DEMB0_AD1: SW5.10(B3) SW5.11(B2) SW5.12(B1) U1.53(DEMB0/AD1) U2.53(DEMB0/AD1) U3.53(DEMB0/AD1) U4.53(DEMB0/AD1)
DEMB1_AD0: SW5.7(B6) SW5.8(B5) SW5.9(B4) U1.54(DEMB1/AD0) U2.54(DEMB1/AD0) U3.54(DEMB1/AD0) U4.54(DEMB1/AD0)
ENSMB: SW2.4(B3) SW2.5(B2) SW2.6(B1) U1.48(ENSMB) U2.48(ENSMB) U3.48(ENSMB) U4.48(ENSMB)
EQA0: SW11.10(B3) SW11.11(B2) SW11.12(B1) U1.20(EQA0) U2.20(EQA0) U3.20(EQA0) U4.20(EQA0)
EQA1: SW11.7(B6) SW11.8(B5) SW11.9(B4) U1.19(EQA1) U2.19(EQA1) U3.19(EQA1) U4.19(EQA1)
EQB0_AD3: SW1.10(B3) SW1.11(B2) SW1.12(B1) U1.46(EQB0/AD3) U2.46(EQB0/AD3) U3.46(EQB0/AD3) U4.46(EQB0/AD3)
EQB1_AD2: SW1.7(B6) SW1.8(B5) SW1.9(B4) U1.47(EQB1/AD2) U2.47(EQB1/AD2) U3.47(EQB1/AD2) U4.47(EQB1/AD2)
JTAG1: J1.B9 J2.B9
JTAG2: J1.A5 J2.A5
JTAG3: J1.A6 J2.A6
JTAG4: J1.A7 J2.A7
JTAG5: J1.A8 J2.A8
LPBK: SW6.7(B6) SW6.8(B5) SW6.9(B4) U1.23(LPBK) U2.23(LPBK) U3.23(LPBK) U4.23(LPBK)
PERN0: C64.1 U1.2(OB_0-)
PERN0_C: C128.1 U1.44(IB_0-)
PERN1: C66.1 U1.4(OB_1-)
PERN1_C: C130.1 U1.42(IB_1-)
PERN2: C68.1 U1.6(OB_2-)
PERN2_C: C132.1 U1.39(IB_2-)
PERN3: C70.1 U1.8(OB_3-)
PERN3_C: C134.1 U1.37(IB_3-)
PERN4: C72.1 U2.2(OB_0-)
PERN4_C: C136.1 U2.44(IB_0-)
PERN5: C74.1 U2.4(OB_1-)
PERN5_C: C138.1 U2.42(IB_1-)
PERN6: C76.1 U2.6(OB_2-)
PERN6_C: C140.1 U2.39(IB_2-)
PERN7: C78.1 U2.8(OB_3-)
PERN7_C: C142.1 U2.37(IB_3-)
PERN8: C80.1 U3.2(OB_0-)
PERN8_C: C144.1 U3.44(IB_0-)
PERN9: C82.1 U3.4(OB_1-)
PERN9_C: C146.1 U3.42(IB_1-)
PERN10: C84.1 U3.6(OB_2-)
PERN10_C: C148.1 U3.39(IB_2-)
PERN11: C86.1 U3.8(OB_3-)
PERN11_C: C150.1 U3.37(IB_3-)
PERN12: C88.1 U4.2(OB_0-)
PERN12_C: C152.1 U4.44(IB_0-)
PERN13: C90.1 U4.4(OB_1-)
PERN13_C: C154.1 U4.42(IB_1-)
PERN14: C92.1 U4.6(OB_2-)
PERN14_C: C156.1 U4.39(IB_2-)
PERN15: C94.1 U4.8(OB_3-)
PERN15_C: C158.1 U4.37(IB_3-)
PERP0: C63.1 U1.1(OB_0+)
PERP0_C: C127.1 U1.45(IB_0+)
PERP1: C65.1 U1.3(OB_1+)
PERP1_C: C129.1 U1.43(IB_1+)
PERP2: C67.1 U1.5(OB_2+)
PERP2_C: C131.1 U1.40(IB_2+)
PERP3: C69.1 U1.7(OB_3+)
PERP3_C: C133.1 U1.38(IB_3+)
PERP4: C71.1 U2.1(OB_0+)
PERP4_C: C135.1 U2.45(IB_0+)
PERP5: C73.1 U2.3(OB_1+)
PERP5_C: C137.1 U2.43(IB_1+)
PERP6: C75.1 U2.5(OB_2+)
PERP6_C: C139.1 U2.40(IB_2+)
PERP7: C77.1 U2.7(OB_3+)
PERP7_C: C141.1 U2.38(IB_3+)
PERP8: C79.1 U3.1(OB_0+)
PERP8_C: C143.1 U3.45(IB_0+)
PERP9: C81.1 U3.3(OB_1+)
PERP9_C: C145.1 U3.43(IB_1+)
PERP10: C83.1 U3.5(OB_2+)
PERP10_C: C147.1 U3.40(IB_2+)
PERP11: C85.1 U3.7(OB_3+)
PERP11_C: C149.1 U3.38(IB_3+)
PERP12: C87.1 U4.1(OB_0+)
PERP12_C: C151.1 U4.45(IB_0+)
PERP13: C89.1 U4.3(OB_1+)
PERP13_C: C153.1 U4.43(IB_1+)
PERP14: C91.1 U4.5(OB_2+)
PERP14_C: C155.1 U4.40(IB_2+)
PERP15: C93.1 U4.7(OB_3+)
PERP15_C: C157.1 U4.38(IB_3+)
PERST: J1.A11 J2.A11
PETN0: C32.2 U1.11(IA_0-)
PETN0_C: C96.2 U1.34(OA_0-)
PETN1: C34.2 U1.13(IA_1-)
PETN1_C: C98.2 U1.32(OA_1-)
PETN2: C36.2 U1.16(IA_2-)
PETN2_C: C100.2 U1.30(OA_2-)
PETN3: C38.2 U1.18(IA_3-)
PETN3_C: C102.2 U1.28(OA_3-)
PETN4: C40.2 U2.11(IA_0-)
PETN4_C: C104.2 U2.34(OA_0-)
PETN5: C42.2 U2.13(IA_1-)
PETN5_C: C106.2 U2.32(OA_1-)
PETN6: C44.2 U2.16(IA_2-)
PETN6_C: C108.2 U2.30(OA_2-)
PETN7: C46.2 U2.18(IA_3-)
PETN7_C: C110.2 U2.28(OA_3-)
PETN8: C48.2 U3.11(IA_0-)
PETN8_C: C112.2 U3.34(OA_0-)
PETN9: C50.2 U3.13(IA_1-)
PETN9_C: C114.2 U3.32(OA_1-)
PETN10: C52.2 U3.16(IA_2-)
PETN10_C: C116.2 U3.30(OA_2-)
PETN11: C54.2 U3.18(IA_3-)
PETN11_C: C118.2 U3.28(OA_3-)
PETN12: C56.2 U4.11(IA_0-)
PETN12_C: C120.2 U4.34(OA_0-)
PETN13: C58.2 U4.13(IA_1-)
PETN13_C: C122.2 U4.32(OA_1-)
PETN14: C60.2 U4.16(IA_2-)
PETN14_C: C124.2 U4.30(OA_2-)
PETN15: C62.2 U4.18(IA_3-)
PETN15_C: C126.2 U4.28(OA_3-)
PETP0: C31.2 U1.10(IA_0+)
PETP0_C: C95.2 U1.35(OA_0+)
PETP1: C33.2 U1.12(IA_1+)
PETP1_C: C97.2 U1.33(OA_1+)
PETP2: C35.2 U1.15(IA_2+)
PETP2_C: C99.2 U1.31(OA_2+)
PETP3: C37.2 U1.17(IA_3+)
PETP3_C: C101.2 U1.29(OA_3+)
PETP4: C39.2 U2.10(IA_0+)
PETP4_C: C103.2 U2.35(OA_0+)
PETP5: C41.2 U2.12(IA_1+)
PETP5_C: C105.2 U2.33(OA_1+)
PETP6: C43.2 U2.15(IA_2+)
PETP6_C: C107.2 U2.31(OA_2+)
PETP7: C45.2 U2.17(IA_3+)
PETP7_C: C109.2 U2.29(OA_3+)
PETP8: C47.2 U3.10(IA_0+)
PETP8_C: C111.2 U3.35(OA_0+)
PETP9: C49.2 U3.12(IA_1+)
PETP9_C: C113.2 U3.33(OA_1+)
PETP10: C51.2 U3.15(IA_2+)
PETP10_C: C115.2 U3.31(OA_2+)
PETP11: C53.2 U3.17(IA_3+)
PETP11_C: C117.2 U3.29(OA_3+)
PETP12: C55.2 U4.10(IA_0+)
PETP12_C: C119.2 U4.35(OA_0+)
PETP13: C57.2 U4.12(IA_1+)
PETP13_C: C121.2 U4.33(OA_1+)
PETP14: C59.2 U4.15(IA_2+)
PETP14_C: C123.2 U4.31(OA_2+)
PETP15: C61.2 U4.17(IA_3+)
PETP15_C: C125.2 U4.29(OA_3+)
PRSNT: SW9.4(A4) SW14.5(B4) SW14.6(B3) SW14.7(B2) SW14.8(B1) U1.52(/PRSNT) U2.52(/PRSNT) U3.52(/PRSNT) U4.52(/PRSNT)
PRSNT1: J1.A1 J2.A1
PRSNT2_1: J1.B17 J2.B17 SW14.1(A1)
PRSNT2_2: J1.B31 J2.B31 SW14.2(A2)
PRSNT2_3: J1.B48 J2.B48 SW14.3(A3)
PRSNT2_4: J1.B81 J2.B81 SW14.4(A4)
RATE: SW10.7(B6) SW10.8(B5) SW10.9(B4) U1.21(RATE) U2.21(RATE) U3.21(RATE) U4.21(RATE)
RD_EN2: SW8.7(B2) SW9.1(A1) U2.26(SD_TH/RD_EN)
RD_EN3: SW8.6(B3) SW9.2(A2) U3.26(SD_TH/RD_EN)
RD_EN4: SW8.5(B4) SW9.3(A3) U4.26(SD_TH/RD_EN)
REFCLKN: J1.A14 J2.A14
REFCLKP: J1.A13 J2.A13
RSV2: J1.B30 J2.B30
RSVD: J1.A19 J2.A19
RSVD1: J1.B12 J2.B12
RSVD2: J1.B82 J2.B82
RSVD3: J1.A32 J2.A32
RSVD4: J1.A33 J2.A33
RSVD5: J1.A50 J2.A50
RXDET: SW10.10(B3) SW10.11(B2) SW10.12(B1) U1.22(RXDET) U2.22(RXDET) U3.22(RXDET) U4.22(RXDET)
SCL: J8.3 J9.6 R55.1 SW4.3(B2) SW12.4(B1)
SD_TH: SW6.10(B3) SW6.11(B2) SW6.12(B1) SW8.1(A1) SW8.2(A2) SW8.3(A3) SW8.4(A4) U1.26(SD_TH/RD_EN)
SDA: J8.4 J9.5 R56.1 SW4.4(B1) SW12.3(B2)
SMCLK: J1.B5 J2.B5 SW12.1(A1)
SMDAT: J1.B6 J2.B6 SW12.2(A2)
VIH: J7.2 J9.8 R11.1 R14.1 R17.1 R20.1 R23.1 R26.1 R29.1 R32.1 R35.1 R38.1 R41.1 R44.1 R47.1 R53.1 R54.2 R55.2 R56.2
VOUT1_2: C27.1 C29.1 J4.2 J4.3 J7.3 R1.2 U5.5(OUTPUT)
VOUT3_4: C28.1 C30.1 J6.2 J6.3 R4.2 U6.5(OUTPUT)
WAKE: J1.B11 J2.B11
N14347575: C29.2 R1.1 R2.2 U5.6(ADJ)
N14347651: C25.1 U5.1(BYPASS)
N14347847: R3.2 U5.8(S_DWN)
N14379250: C26.1 U6.1(BYPASS)
N14379574: C30.2 R4.1 R5.2 U6.6(ADJ)
N14379914: R6.2 U6.8(S_DWN)
N14519010: R53.2 SW8.8(B1) SW13.1
N14524358: J9.3 R52.2
N14524360: J9.2 R51.2
N14524362: J9.1 R50.2
N14693554: J9.7 R54.1
N143603151: R14.2 SW1.4(A4)
N143603431: R15.2 SW1.5(A5)
N143603671: R13.2 SW1.3(A3)
N143605131: R12.2 SW1.2(A2)
N143605431: R16.2 SW1.6(A6)
N143605671: R11.2 SW1.1(A1)
N144765660: C109.1 J2.B45
N144766261: C142.2 J2.A48
N144766561: C153.2 J2.A72
N144766980: C99.1 J2.B23
N144767221: C158.2 J2.A81
N144767760: C123.1 J2.B74
N144768181: C132.2 J2.A26
N144768421: C130.2 J2.A22
N144768781: C147.2 J2.A60
N144769021: C143.2 J2.A52
N144769680: C95.1 J2.B14
N144769921: C154.2 J2.A73
N144770280: C106.1 J2.B38
N144770640: C115.1 J2.B58
N144770880: C116.1 J2.B59
N144771181: C137.2 J2.A39
N144771420: C108.1 J2.B42
N144771900: C102.1 J2.B28
N144772140: C125.1 J2.B78
N144772500: C120.1 J2.B67
N144772741: C149.2 J2.A64
N144773341: C141.2 J2.A47
N144773581: C133.2 J2.A29
N144774000: C124.1 J2.B75
N144774240: C117.1 J2.B62
N144774480: C98.1 J2.B20
N144775140: C110.1 J2.B46
N144775501: C156.2 J2.A77
N144776160: C114.1 J2.B55
N144776640: C100.1 J2.B24
N144776880: C97.1 J2.B19
N144777181: C151.2 J2.A68
N144777421: C150.2 J2.A65
N144777781: C144.2 J2.A53
N144778201: C146.2 J2.A57
N144778500: C122.1 J2.B71
N144778741: C148.2 J2.A61
N144778981: C140.2 J2.A44
N144779220: C103.1 J2.B33
N144779460: C101.1 J2.B27
N144780060: C121.1 J2.B70
N144780361: C139.2 J2.A43
N144780601: C138.2 J2.A40
N144788221: C157.2 J2.A80
N144788821: C145.2 J2.A56
N144789240: C111.1 J2.B50
N144789780: C107.1 J2.B41
N144790260: C118.1 J2.B63
N144790620: C104.1 J2.B34
N144791101: C129.2 J2.A21
N144791880: C126.1 J2.B79
N144792241: C127.2 J2.A16
N144792841: C135.2 J2.A35
N144793080: C119.1 J2.B66
N144793501: C128.2 J2.A17
N144794040: C113.1 J2.B54
N144794401: C131.2 J2.A25
N144794701: C134.2 J2.A30
N144795060: C96.1 J2.B15
N144795421: C155.2 J2.A76
N144795720: C112.1 J2.B51
N144796260: C105.1 J2.B37
N144796741: C152.2 J2.A69
N144796981: C136.2 J2.A36
N144870501: R19.2 SW2.3(A3)
N144870781: R17.2 SW2.1(A1)
N144871281: R18.2 SW2.2(A2)
N144872111: R25.2 SW3.6(A6)
N144872810: R20.2 SW3.1(A1)
N144872811: R21.2 SW3.2(A2)
N144872812: R22.2 SW3.3(A3)
N144872813: R23.2 SW3.4(A4)
N144872814: R24.2 SW3.5(A5)
N144873671: R29.2 SW5.4(A4)
N144874091: R31.2 SW5.6(A6)
N144874331: R30.2 SW5.5(A5)
N144874811: R28.2 SW5.3(A3)
N144875811: R26.2 SW5.1(A1)
N144876491: R27.2 SW5.2(A2)
N144883340: R38.2 SW10.1(A1)
N144883341: R39.2 SW10.2(A2)
N144883342: R40.2 SW10.3(A3)
N144883343: R41.2 SW10.4(A4)
N144883344: R42.2 SW10.5(A5)
N144883345: R43.2 SW10.6(A6)
N144883781: R44.2 SW11.1(A1)
N144885701: R35.2 SW6.4(A4)
N144886021: R45.2 SW11.2(A2)
N144886681: R37.2 SW6.6(A6)
N144886921: R36.2 SW6.5(A5)
N144888121: R34.2 SW6.3(A3)
N144888661: R49.2 SW11.6(A6)
N144889101: R46.2 SW11.3(A3)
N144890181: R47.2 SW11.4(A4)
N144890984: R48.2 SW11.5(A5)
N144891221: R32.2 SW6.1(A1)
N144891941: R33.2 SW6.2(A2)
N144905650: D1.2(ANODE) R7.1
N144909880: D3.2(ANODE) R9.1
N144912360: D2.2(ANODE) R8.1
N144914850: D4.2(ANODE) R10.1
N708449615: C63.2 J1.A16
N708449616: C64.2 J1.A17
N708449620: C65.2 J1.A21
N708449621: C66.2 J1.A22
N708449624: C67.2 J1.A25
N708449625: C68.2 J1.A26
N708449628: C69.2 J1.A29
N708449629: C70.2 J1.A30
N708449634: C71.2 J1.A35
N708449635: C72.2 J1.A36
N708449638: C73.2 J1.A39
N708449639: C74.2 J1.A40
N708449642: C75.2 J1.A43
N708449643: C76.2 J1.A44
N708449646: C77.2 J1.A47
N708449647: C78.2 J1.A48
N708449651: C79.2 J1.A52
N708449652: C80.2 J1.A53
N708449655: C81.2 J1.A56
N708449656: C82.2 J1.A57
N708449659: C83.2 J1.A60
N708449660: C84.2 J1.A61
N708449663: C85.2 J1.A64
N708449664: C86.2 J1.A65
N708449667: C87.2 J1.A68
N708449668: C88.2 J1.A69
N708449671: C89.2 J1.A72
N708449672: C90.2 J1.A73
N708449675: C91.2 J1.A76
N708449676: C92.2 J1.A77
N708449679: C93.2 J1.A80
N708449680: C94.2 J1.A81
N708449695: C31.1 J1.B14
N708449696: C32.1 J1.B15
N7084496100: C33.1 J1.B19
N7084496101: C34.1 J1.B20
N7084496104: C35.1 J1.B23
N7084496105: C36.1 J1.B24
N7084496108: C37.1 J1.B27
N7084496109: C38.1 J1.B28
N7084496114: C39.1 J1.B33
N7084496115: C40.1 J1.B34
N7084496118: C41.1 J1.B37
N7084496119: C42.1 J1.B38
N7084496122: C43.1 J1.B41
N7084496123: C44.1 J1.B42
N7084496126: C45.1 J1.B45
N7084496127: C46.1 J1.B46
N7084496131: C47.1 J1.B50
N7084496132: C48.1 J1.B51
N7084496135: C49.1 J1.B54
N7084496136: C50.1 J1.B55
N7084496139: C51.1 J1.B58
N7084496140: C52.1 J1.B59
N7084496143: C53.1 J1.B62
N7084496144: C54.1 J1.B63
N7084496147: C55.1 J1.B66
N7084496148: C56.1 J1.B67
N7084496151: C57.1 J1.B70
N7084496152: C58.1 J1.B71
N7084496155: C59.1 J1.B74
N7084496156: C60.1 J1.B75
N7084496159: C61.1 J1.B78
N7084496160: C62.1 J1.B79

Pads without a net: J8 2; U5 2 7; U6 2 7

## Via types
v1: diameter 0.508, hole 0.254, TOP to BOTTOM, 474 vias

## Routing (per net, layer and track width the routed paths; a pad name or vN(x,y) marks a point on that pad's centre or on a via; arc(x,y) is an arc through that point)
12V: length 35.5
  TOP w0.635: J2.A2 46.65,57.81 v1(46.65,57.81) ; v1(46.65,57.81) 45.23,57.81 45.65,58.23 J2.B1 ; v1(46.65,57.81) 46.67,57.82 v1(47.65,57.82) J2.A3 ; v1(46.65,6.55) 47.64,6.55 v1(47.65,6.54) J1.A3 ; v1(46.65,6.55) 46.5,6.7 v1(46.5,7.36) 45.65,6.52 J1.B1 ; v1(46.65,6.55) J1.A2
  BOTTOM w0.508: v1(45.12,57.68) 45.17,57.73 46.57,57.73 v1(46.65,57.81) 46.65,57.81
  BOTTOM w0.635: v1(46.65,57.81) 47.64,57.81 v1(47.65,57.82) J2.A3 ; J1.A3 v1(47.65,6.54) ; J1.A2 v1(46.65,6.55) ; J2.A2 46.65,57.81
GND: length 449.3
  TOP w0.305: 64.58,60.18 J2.A18 ; v1(78.8,56.74) 78.8,56.75 78.8,57.2 78.8,57.21 78.8,57.65 78.8,57.65 78.8,58.36 78.65,58.52 J2.B32
  TOP w0.381: U6.3 v1(84.9,38.63) ; U5.3 v1(84.11,19.96) ; v1(64.58,57.07) 64.58,60.18 ; R5.1 v1(90.61,41.68) ; D2.1 93.22,47.62 v1(93.24,47.6) ; v1(74.92,57.83) 75.65,58.56 J2.B29 ; C24.1 v1(80.86,40.18)
  TOP w0.508: J1.B57 103.65,6.1 v1(104.13,6.58) ; J2.B68 114.65,58.35 v1(114.16,57.86) ; J1.B80 126.65,6.02 v1(126.1,6.58) ; J2.B52 98.65,58.25 98.16,57.76 98.08,57.76 v1(98.08,57.75) ; C28.2 v1(94.12,33.27) ; J1.B32 78.65,6.12 v1(78.17,6.6) ; v1(62.12,58.04) 62.19,58.04 62.65,58.49 J2.B16 ; J1.B29 75.65,6 v1(75.15,6.5) ; v1(106.14,57.86) 106.65,58.37 J2.B60 ; v1(83.15,6.58) 82.65,6.08 J1.B36 ; v1(87.08,6.65) 86.65,6.22 J1.B40 ; J1.B47 93.65,6.08 v1(93.15,6.58) ; J1.B69 115.65,6.16 v1(116.12,6.63) ; J2.B73 119.65,58.26 v1(120.09,57.82) ; J2.B65 111.65,58.34 v1(112.16,57.83) ; v1(91.12,6.65) 90.65,6.18 J1.B44 ; J2.B57 103.65,58.29 v1(104.1,57.83) ; v1(73.04,57.91) 72.65,58.3 J2.B26 ; J1.B26 72.65,6.14 v1(73.13,6.61) ; J2.B72 118.65,58.33 v1(118.15,57.83) ; v1(81.14,6.58) 81.65,6.07 J1.B35 ; J1.B68 114.65,5.96 v1(114.03,6.58) ; J1.B64 110.65,6 v1(110.07,6.58) ; v1(69.13,6.58) 68.65,6.1 J1.B22 ; J2.B25 71.65,58.45 v1(71.08,57.88) ; J1.B61 107.65,6.08 v1(108.09,6.52) ; J2.B35 81.65,58.49 81.14,57.98 v1(81.12,57.98) ; J1.B43 89.65,5.84 v1(88.96,6.52) ; v1(89.09,57.81) 89.65,58.36 J2.B43 ; J1.B21 67.65,6.02 v1(67.09,6.58) ; J2.B61 107.65,58.25 v1(108.09,57.81) ; v1(124.12,57.88) 123.65,58.35 J2.B77 ; v1(83.1,57.88) 83.1,57.91 82.65,58.36 J2.B36 ; J2.B7 51.65,57.91 v1(51.2,57.45) ; J2.B47 93.65,58.38 v1(93.18,57.91) ; J1.B72 118.65,6.07 v1(118.1,6.63) ; J1.B39 85.65,5.88 v1(84.98,6.55) ; J1.B65 111.65,6.1 v1(112.1,6.55) ; J1.B52 98.65,6.08 v1(98.08,6.65) ; v1(106.08,6.55) 106.65,5.98 J1.B60 ; v1(126.07,57.88) 126.65,58.46 J2.B80 ; J2.B56 102.65,58.28 v1(102.12,57.76) ; v1(110.15,57.88) 110.65,58.38 J2.B64 ; v1(69.2,57.86) 69.15,57.86 68.65,58.36 J2.B22 ; v1(67.15,57.91) 67.22,57.91 67.65,58.34 J2.B21 ; v1(120.1,6.63) 119.65,6.17 J1.B73 ; v1(91.1,57.86) 90.65,58.31 J2.B44 ; J2.B40 86.65,58.34 87.11,57.88 v1(87.19,57.88) ; J2.B76 122.65,58.4 v1(122.11,57.86) ; v1(124.02,6.58) 123.65,6.21 J1.B77 ; J1.B13 v1(59.65,6.8) ; J1.A49 95.65,6.29 v1(95.34,6.6) ; v1(71.01,6.58) 71.65,5.94 J1.B25 ; v1(100.09,6.65) 99.65,6.21 J1.B53 ; J1.B56 102.65,5.94 v1(102.02,6.58) ; J1.A4 v1(48.65,6.54) ; v1(62.14,6.65) 62.65,6.14 J1.B16 ; v1(85.1,57.83) 85.65,58.38 J2.B39 ; v1(58.99,57.83) 59.65,58.49 J2.B13 ; J1.B7 v1(51.65,6.68) ; D3.1 v1(134.05,45.27) ; J2.A4 v1(48.65,57.81) ; v1(95.65,57.98) J2.A49 ; J1.B76 122.65,5.99 v1(122.09,6.55) ; J2.B53 99.65,58.35 v1(100.14,57.86) ; D4.1 v1(136.97,45.37) ; J2.B69 115.65,58.33 v1(116.12,57.86)
  TOP w0.635: v1(64.68,6.42) 64.65,6.39 J1.A18 ; v1(93.27,49.76) 93.24,49.78 D1.1 ; R2.1 v1(93.03,22.48)
  TOP w0.762: v1(94.37,13.56) C27.2 v1(93.33,12.6) ; SW7.2 v1(89.85,33.04) ; SW7.1 v1(89.73,30.5)
  BOTTOM w0.305: J2.A18 64.58,60.18 v1(64.58,57.07)
  BOTTOM w0.381: C161.1 v1(94.95,41.95) ; C26.2 v1(84.15,41.92)
  BOTTOM w0.508: J2.A23 69.65,58.3 v1(69.2,57.86) ; v1(114.03,6.58) 113.65,6.19 J1.A67 ; J2.A38 84.65,58.29 v1(85.1,57.83) ; J2.A12 58.65,58.18 v1(58.99,57.83) ; v1(95.34,6.6) 95.65,6.29 J1.A49 ; v1(126.1,6.58) 125.65,6.13 J1.A79 ; v1(91.1,57.86) 91.65,58.41 J2.A45 ; J2.A82 128.65,58.41 v1(129.36,57.7) ; J1.A82 128.65,6.87 v1(127.85,7.67) ; J1.A46 92.65,6.07 v1(93.15,6.58) ; C25.2 86.69,21.67 87.14,21.23 v1(87.57,21.23) ; J2.A34 80.65,58.45 v1(81.12,57.98) ; v1(93.18,57.91) 93.18,57.93 92.65,58.47 J2.A46 ; J1.A18 64.65,6.39 v1(64.68,6.42) ; v1(67.15,57.91) 67.02,57.91 66.65,58.28 J2.A20 ; J2.A70 116.65,58.39 v1(116.12,57.86) ; v1(118.1,6.63) 117.65,6.18 J1.A71 ; J1.A24 70.65,6.22 v1(71.01,6.58) ; J1.A74 120.65,6.08 v1(120.1,6.63) ; J1.A23 69.65,6.05 v1(69.13,6.58) ; v1(108.09,57.81) 108.65,58.37 J2.A62 ; J1.A27 73.65,6.09 v1(73.13,6.61) ; v1(102.12,57.76) 101.65,58.23 J2.A55 ; J2.A51 97.65,58.19 98.08,57.77 v1(98.08,57.75) ; v1(112.1,6.55) 112.65,6 J1.A66 ; v1(67.09,6.58) 66.65,6.13 J1.A20 ; v1(83.1,57.88) 83.65,58.44 J2.A37 ; J1.A75 121.65,6.11 v1(122.09,6.55) ; J2.A42 88.65,58.25 v1(89.09,57.81) ; J1.A15 61.65,5.83 62.14,6.32 v1(62.14,6.65) ; J1.A58 104.65,6.05 v1(104.13,6.58) ; J1.A42 88.65,6.21 v1(88.96,6.52) ; v1(87.08,6.65) 87.65,6.09 J1.A41 ; v1(74.92,57.83) 74.65,58.1 J2.A28 ; J1.A78 124.65,5.94 v1(124.02,6.58) ; J2.A78 124.65,58.41 v1(124.12,57.88) ; R49.1 v1(157.6,31.43) ; v1(110.07,6.58) 109.65,6.15 J1.A63 ; J1.A62 108.65,5.96 v1(108.09,6.52) ; v1(118.15,57.83) 117.65,58.33 J2.A71 ; J2.A49 v1(95.65,57.98) ; J2.A74 120.65,58.38 v1(120.09,57.82) ; J1.A55 101.65,6.21 v1(102.02,6.58) ; v1(59.65,6.8) 58.65,5.8 J1.A12 ; J1.A4 v1(48.65,6.54) ; J2.A58 104.65,58.38 v1(104.1,57.83) ; v1(81.14,6.58) 80.65,6.08 J1.A34 ; R48.1 v1(157.73,28.89) ; J1.A45 91.65,6.12 v1(91.12,6.65) ; R51.1 v1(144.07,20.61) ; J1.A28 74.65,6 v1(75.15,6.5) ; J2.A59 105.65,58.34 v1(106.14,57.86) ; J1.A59 105.65,6.12 v1(106.08,6.55) ; J2.A75 121.65,58.32 v1(122.11,57.86) ; v1(110.15,57.88) 109.65,58.38 J2.A63 ; R52.1 v1(144.04,23.15) ; J2.A66 112.65,58.33 v1(112.16,57.83) ; J2.A31 77.65,58.3 v1(77.15,57.81) ; J1.A54 100.65,6.09 v1(100.09,6.65) ; J1.A51 97.65,6.22 v1(98.08,6.65) ; J2.A24 70.65,58.34 71.08,57.91 v1(71.08,57.88) ; J2.A27 73.65,58.52 v1(73.04,57.91) ; J2.A79 125.65,58.31 v1(126.07,57.88) ; R45.1 v1(157.85,21.27) ; v1(100.14,57.86) 100.65,58.37 J2.A54 ; v1(114.16,57.86) 113.65,58.37 J2.A67 ; J1.A38 84.65,6.22 v1(84.98,6.55) ; R50.1 v1(133.74,18.06) ; J2.A41 87.65,58.35 v1(87.19,57.88) ; v1(83.15,6.58) 83.65,6.07 J1.A37 ; R46.1 v1(157.73,23.81) ; J1.A70 116.65,6.09 v1(116.12,6.63) ; J2.A4 v1(48.65,57.81) ; C22.1 v1(100.27,43.71)
  BOTTOM w0.635: R39.1 v1(156.91,40.1) ; R22.1 v1(22.67,35.71) ; C21.1 v1(100.01,28.47) ; R42.1 v1(156.71,47.7) ; R18.1 v1(22.92,48.79) ; v1(78.17,6.6) 77.65,6.08 J1.A31 ; R21.1 v1(20.13,35.71) ; R15.1 v1(21.53,58.82) ; J2.A15 61.65,58.48 62.09,58.04 v1(62.12,58.04) ; R12.1 v1(29.02,58.82) ; R34.1 v1(144.68,54.7) ; R25.1 v1(30.29,35.71) ; R13.1 v1(26.48,58.82) ; R31.1 v1(30.54,23.26) ; C160.1 v1(95.31,27.5) ; v1(84.11,19.96) 85.39,19.96 C23.1 ; R40.1 v1(157.09,42.64) ; R28.1 v1(22.92,23.26) ; R24.1 v1(27.75,35.71) ; R37.1 v1(144.5,62.34) ; R16.1 v1(18.86,58.82) ; R43.1 v1(156.81,50.26) ; R19.1 v1(20.26,48.79) ; R27.1 v1(20.38,23.26) ; R36.1 v1(144.57,59.8) ; R33.1 v1(144.59,52.15) ; R30.1 v1(28,23.26)
  vias: v1(54.01,34.69) v1(55.28,36.09) v1(55.28,34.69) v1(55.28,33.3) v1(56.81,36.09) v1(56.81,34.69) v1(56.81,33.3) v1(58.27,36.09) v1(58.27,34.69) v1(58.27,33.3) v1(59.79,36.09) v1(59.79,34.69) v1(59.79,33.3) v1(60.87,34.69) v1(70.02,34.69) v1(71.29,36.09) v1(71.29,34.69) v1(71.29,33.3) v1(72.81,36.09) v1(72.81,34.69) v1(72.81,33.3) v1(74.27,36.09) v1(74.27,34.69) v1(74.27,33.3) v1(75.79,36.09) v1(75.79,34.69) v1(75.79,33.3) v1(76.87,34.69) v1(84.9,39.9) v1(86.17,39.9) v1(86.17,38.63) v1(87.57,19.96) v1(88.84,21.23) v1(88.84,19.96) v1(104.7,34.69) v1(105.85,36.09) v1(105.85,34.69) v1(105.85,33.3) v1(107.38,36.09) v1(107.38,34.69) v1(107.38,33.3) v1(108.84,36.09) v1(108.84,34.69) v1(108.84,33.3) v1(110.36,36.09) v1(110.36,34.69) v1(110.36,33.3) v1(111.44,34.69) v1(120.59,34.69) v1(121.86,36.09) v1(121.86,34.69) v1(121.86,33.3) v1(123.38,36.09) v1(123.38,34.69) v1(123.38,33.3) v1(124.84,36.09) v1(124.84,34.69) v1(124.84,33.3) v1(126.37,36.09) v1(126.37,34.69) v1(126.37,33.3) v1(127.44,34.69)
VDD1: length 7.8
  TOP w0.229: U1.51 v1(51.74,34.19)
  TOP w0.254: v1(57.7,38.12) 57.72,38.12 57.69,38.09 U1.36 ; U1.41 v1(55.19,38.12) ; U1.14 v1(59.69,31.26) ; U1.9 v1(57.19,31.26)
  BOTTOM w0.292: v1(55.19,38.12) 55.31,38.01 C4.2 ; C5.2 59.73,31.3 v1(59.69,31.26) ; v1(51.74,34.19) 51.75,34.19 C2.2 ; C1.2 57.19,31.27 v1(57.19,31.26) ; v1(57.7,38.12) 57.72,38.1 C3.2
VDD2: length 8.3
  TOP w0.229: U2.51 v1(67.63,34.19)
  TOP w0.254: U2.36 v1(73.69,38.15) ; U2.14 v1(75.69,31.24) ; U2.41 v1(71.19,38.12) ; U2.9 v1(73.19,31.24)
  BOTTOM w0.292: v1(67.63,34.19) 67.63,34.19 C8.2 ; C10.2 75.73,31.27 v1(75.69,31.24) ; v1(73.19,31.24) 73.19,31.24 C9.2 ; v1(73.69,38.15) 73.7,38.14 C6.2 ; v1(71.19,38.12) 71.16,38.09 C7.2
VDD3: length 8.2
  TOP w0.229: U3.51 v1(102.2,34.19)
  TOP w0.254: U3.14 v1(110.26,31.24) ; U3.9 v1(107.76,31.24) ; U3.41 v1(105.76,38.11) ; v1(108.26,38.12) 108.29,38.12 108.26,38.1 U3.36
  BOTTOM w0.292: C14.2 108.27,38.12 v1(108.26,38.12) ; C12.2 107.76,31.24 v1(107.76,31.24) ; C11.2 110.3,31.27 v1(110.26,31.24) ; v1(105.76,38.11) 105.73,38.07 C15.2 ; v1(102.2,34.19) 102.2,34.19 102.69,34.19 103,34.19 103,34.19 C13.2
VDD4: length 8.1
  TOP w0.229: U4.51 v1(118.2,34.19)
  TOP w0.254: U4.41 v1(121.77,38.15) ; U4.36 v1(124.27,38.12) ; U4.9 v1(123.77,31.24) ; U4.14 v1(126.27,31.24)
  BOTTOM w0.292: v1(118.2,34.19) 118.21,34.19 C18.2 ; C17.2 123.61,31.4 v1(123.77,31.24) ; v1(121.77,38.15) 121.73,38.11 C20.2 ; v1(124.27,38.12) 124.27,38.12 C19.2 ; v1(126.27,31.24) 126.38,31.35 C16.2
VDD_SEL1_2: length 32.1
  TOP w0.229: U1.25 v1(63.99,35.69) ; U2.25 v1(79.99,35.69)
  TOP w0.762: SW7.4 81.52,30.5 v1(80.91,31.11)
  POWER1 w0.229: 78.19,36.98 78.19,36.24 78.74,35.69 v1(79.99,35.69) ; 64.58,35.81 64.46,35.69 v1(63.99,35.69)
  POWER1 w0.292: 78.19,36.98 78.19,37.11 78.25,37.16 ; 65.21,38.17 65.11,38.07 65.11,36.34 64.58,35.81
  POWER1 w0.762: 65.21,38.17 66.54,39.49 76.77,39.49 78.25,38.02 78.25,37.16
  BOTTOM w0.508: 80.84,34.85 v1(79.99,35.69)
  BOTTOM w0.762: 80.84,34.85 81.17,34.52 81.17,31.37 v1(80.91,31.11)
VDD_SEL3_4: length 63.8
  TOP w0.229: U4.25 v1(130.56,35.69) ; U3.25 v1(114.56,35.69)
  TOP w0.762: SW7.3 v1(85.18,33.04)
  POWER1 w0.229: v1(114.56,35.69) 114.56,35.69 113.47,35.69
  POWER1 w0.292: 99.11,32.52 99.63,32 102.67,32 103.08,32.41 ; 113.47,35.69 112.58,35.69
  POWER1 w0.508: 112.58,35.69 112.33,35.69 111.93,36.09 ; 99.11,32.52 97.63,34.01
  POWER1 w0.635: 111.93,36.09 111.27,36.75 ; 97.63,34.01 96.84,34.79
  POWER1 w0.762: v1(85.18,33.04) 87.57,35.43 96.2,35.43 96.84,34.79 ; 111.27,36.75 110.76,37.26 105.58,37.26 104.25,35.93 104.25,35.5 103.7,34.95 103.7,33.02 103.08,32.41
  BOTTOM w0.229: v1(130.56,35.69) 129.59,35.69 129.27,36.01 129.27,36.7
  BOTTOM w0.292: 115.79,37.79 115.79,36.4 115.08,35.69 v1(114.56,35.69)
  BOTTOM w0.508: 115.79,37.79 115.79,38.56 117.75,40.51 126.66,40.51 129.27,37.89 129.27,36.7
